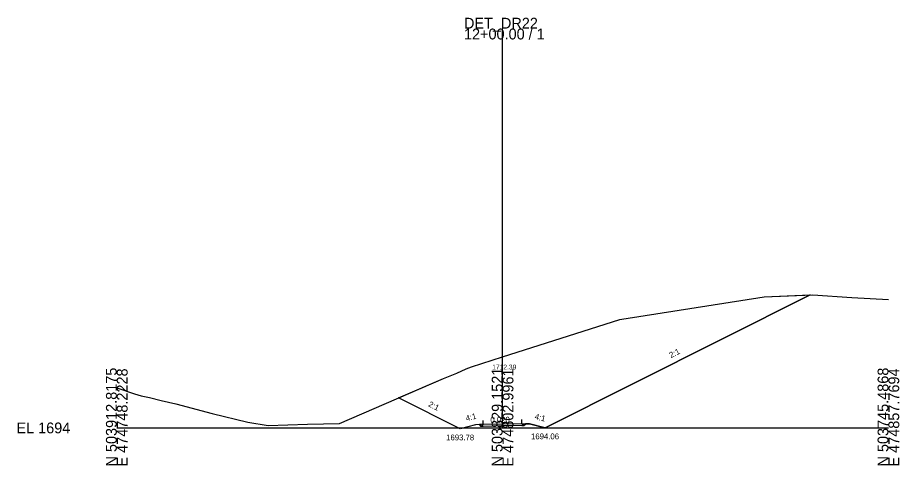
# Model space of a CAD drawing. Extents: x -26 to 1203, y -10 to 9633.
# Drawn here: x -25.7 to 202.8, y 4990.3 to 5106.2 of the extents above; entities that cross this region are included whole.
import ezdxf

# ---------------------------------------------------------------- set-up
doc = ezdxf.new("R2010")
doc.units = 0
for name, color, linetype in [('Exist Cross Section Cell', 7, 'Continuous'), ('Exist XS Center Line Elevation Label', 7, 'Continuous'), ('Exist XS Ground Line', 7, 'Continuous'), ('Prop XS Ditch Slope Text', 7, 'Continuous'), ('Prop XS Ditch Standard Text', 7, 'Continuous'), ('Prop XS Earthwork Shape', 7, 'Continuous'), ('Prop XS EOT Tick Mark', 7, 'Continuous'), ('Prop XS Finish Grade', 7, 'Continuous'), ('Prop XS Finish Grade Earthwork', 7, 'Continuous'), ('Prop XS Finish Grade Pavement', 7, 'Continuous'), ('Prop XS Pvmt Edge Slope', 7, 'Continuous'), ('Prop XS SE Text', 7, 'Continuous'), ('Prop XS Shoulder Borrow Shape', 7, 'Continuous'), ('Prop XS Side Slope Text', 7, 'Continuous'), ('Prop XS Subgrade Earthwork', 7, 'Continuous')]:
    doc.layers.add(name, color=color, linetype=linetype)

msp = doc.modelspace()

# ---------------------------------------------------------------- linework, layer by layer
at = {"layer": 'Exist Cross Section Cell'}
for p, q in [((100, 5000), (100, 5103.41)), ((0, 5000), (100, 5000)), ((100, 5000), (200, 5000))]:
    msp.add_line(p, q, dxfattribs=at)
at = {"layer": 'Exist XS Ground Line'}
msp.add_lwpolyline([(0, 5010.38), (4.56, 5008.79), (6.33, 5008.31), (8.47, 5007.91), (11.47, 5007.12), (15.35, 5006.27), (24.72, 5003.71), (33.94, 5001.53), (39.2, 5000.67), (49.47, 5000.93), (57.69, 5001.18), (84.68, 5012.79), (88.13, 5014.16), (90.57, 5015.34), (91.97, 5015.82), (100, 5018.39), (130.42, 5028.1), (130.89, 5028.17), (167.77, 5033.91), (180.43, 5034.47), (190.5, 5033.8), (200, 5033.23)], dxfattribs=at)
at = {"layer": 'Prop XS Earthwork Shape'}
msp.add_lwpolyline([(89, 4999.78), (73.01, 5007.77), (84.68, 5012.79), (88.13, 5014.16), (90.57, 5015.34), (91.97, 5015.82), (100, 5018.39), (130.42, 5028.1), (130.89, 5028.17), (167.77, 5033.91), (179.76, 5034.44), (111, 5000.06), (107, 5001.06), (106.02, 5001.1), (105.53, 5000.61), (105, 5000.6), (100, 5000.5), (95, 5000.4), (94.45, 5000.39), (93.98, 5000.86), (93, 5000.78)], close=True, dxfattribs=at)
at = {"layer": 'Prop XS EOT Tick Mark'}
for p, q in [((95, 5000.94), (95, 5001.94)), ((105, 5001.14), (105, 5002.14))]:
    msp.add_line(p, q, dxfattribs=at)
at = {"layer": 'Prop XS Finish Grade'}
for p, q in [((95, 5000.94), (93.98, 5000.86)), ((105, 5001.14), (106.02, 5001.1))]:
    msp.add_line(p, q, dxfattribs=at)
at = {"layer": 'Prop XS Finish Grade Earthwork'}
for p, q in [((111, 5000.06), (179.76, 5034.44)), ((89, 4999.78), (73.01, 5007.77)), ((93, 5000.78), (89, 4999.78)), ((93.98, 5000.86), (93, 5000.78)), ((106.02, 5001.1), (107, 5001.06)), ((107, 5001.06), (111, 5000.06))]:
    msp.add_line(p, q, dxfattribs=at)
at = {"layer": 'Prop XS Finish Grade Pavement'}
for p, q in [((95, 5000.94), (100, 5001.04)), ((100, 5001.04), (105, 5001.14))]:
    msp.add_line(p, q, dxfattribs=at)
at = {"layer": 'Prop XS Pvmt Edge Slope'}
for p, q in [((95, 5000.94), (94.45, 5000.39)), ((105, 5001.14), (105.53, 5000.61))]:
    msp.add_line(p, q, dxfattribs=at)
at = {"layer": 'Prop XS Shoulder Borrow Shape'}
for points in [[(95, 5000.94), (93.98, 5000.86), (94.45, 5000.39)], [(105, 5001.14), (106.02, 5001.1), (105.53, 5000.61)]]:
    msp.add_lwpolyline(points, close=True, dxfattribs=at)
at = {"layer": 'Prop XS Subgrade Earthwork'}
for p, q in [((94.45, 5000.39), (93.98, 5000.86)), ((95, 5000.4), (94.45, 5000.39)), ((100, 5000.5), (95, 5000.4)), ((105, 5000.6), (100, 5000.5)), ((105, 5000.6), (105.53, 5000.61)), ((105.53, 5000.61), (106.02, 5001.1))]:
    msp.add_line(p, q, dxfattribs=at)

# ---------------------------------------------------------------- texts
at = {"layer": 'Exist Cross Section Cell'}
for s, p in [('DET_DR22', (90, 5103.41)), ('12+00.00 / 1', (90, 5100.61)), ('EL 1694', (-26, 4998.6))]:
    msp.add_text(s, height=2.8, dxfattribs=at).set_placement(p)
for s, p in [('N 503912.8175', (0, 4990)), ('E 474748.2228', (2.8, 4990)), ('N 503829.1521', (100, 4990)), ('E 474802.9961', (102.8, 4990)), ('N 503745.4868', (200, 4990)), ('E 474857.7694', (202.8, 4990))]:
    msp.add_text(s, height=2.8, rotation=90, dxfattribs=at).set_placement(p)
at = {"layer": 'Exist XS Center Line Elevation Label'}
msp.add_text('1712.39', height=1.25, dxfattribs=at).set_placement((97.31, 5015.14))
at = {"layer": 'Prop XS Ditch Slope Text'}
for rotation, p in [(14.0362, (90.64, 5001.73)), (345.9638, (108.21, 5002.3))]:
    msp.add_text('4:1', height=1.5, rotation=rotation, dxfattribs=at).set_placement(p)
at = {"layer": 'Prop XS Ditch Standard Text'}
for s, p in [('1693.78', (85.38, 4996.78)), ('1694.06', (107.38, 4997.06))]:
    msp.add_text(s, height=1.5, dxfattribs=at).set_placement(p)
at = {"layer": 'Prop XS SE Text'}
msp.add_text('0.020', height=1.5, rotation=1.1458, dxfattribs=at).set_placement((96.85, 5001.3))
at = {"layer": 'Prop XS Side Slope Text'}
for rotation, p in [(26.5651, (143.64, 5018.06)), (333.4349, (80.61, 5005.65))]:
    msp.add_text('2:1', height=1.5, rotation=rotation, dxfattribs=at).set_placement(p)

doc.saveas('drawing.dxf')
